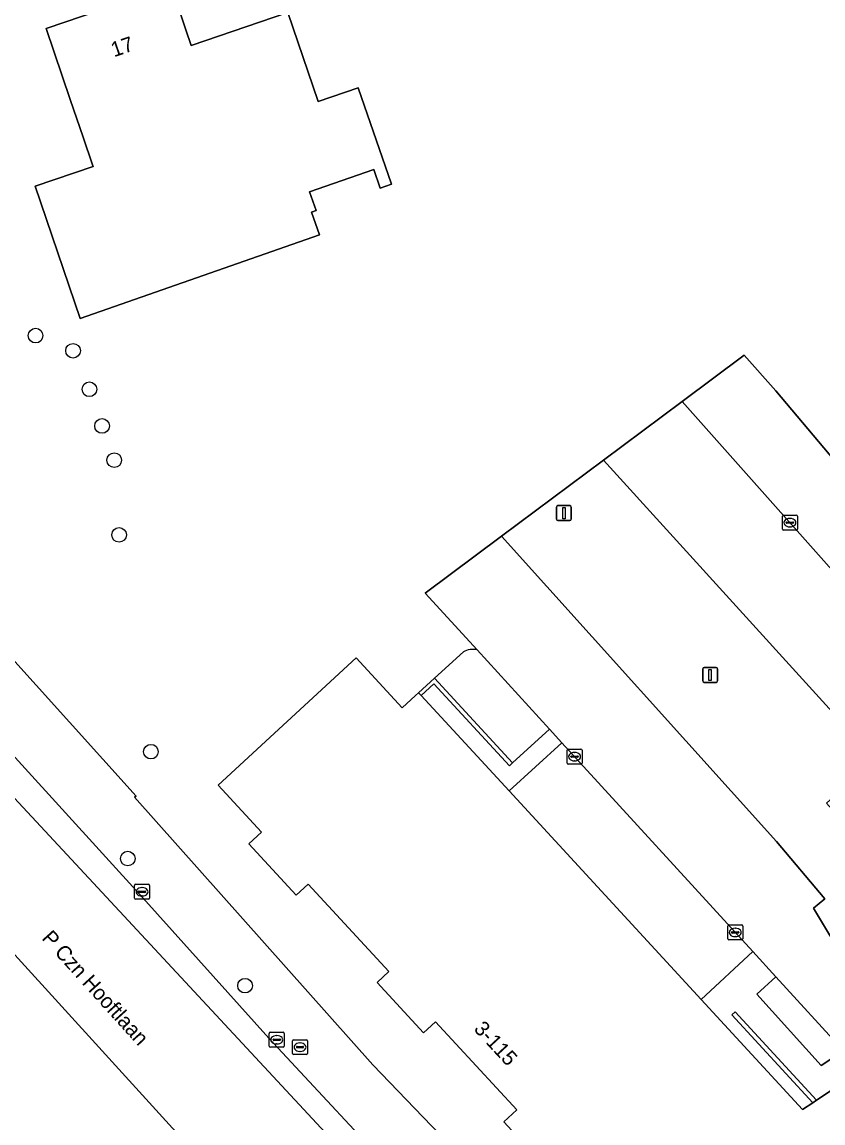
# Model space of a CAD drawing. Extents: x 161087 to 161926, y 382572 to 383873.
# Drawn here: x 161601.8 to 161655.3, y 382684.1 to 382757.7 of the extents above; entities that cross this region are included whole.
import ezdxf

# ---------------------------------------------------------------- set-up
doc = ezdxf.new("R2010")
doc.units = 0
for name, color, linetype in [('IMGEO_Boom', 7, 'Continuous'), ('IMGEO_Erf', 7, 'Continuous'), ('IMGEO_Groenvoorziening', 7, 'Continuous'), ('IMGEO_Kolk', 7, 'Continuous'), ('IMGEO_Lichtmast', 7, 'Continuous'), ('IMGEO_Muur', 7, 'Continuous'), ('IMGEO_Openbare_ruimte_label', 7, 'Continuous'), ('IMGEO_Pand', 7, 'Continuous'), ('IMGEO_Pand_nummerreeks', 7, 'Continuous'), ('IMGEO_Parkeervlak_open', 7, 'Continuous'), ('IMGEO_Rijbaan_lokaal_gesloten', 7, 'Continuous'), ('IMGEO_Rijbaan_lokaal_open', 7, 'Continuous'), ('IMGEO_Rioolput', 7, 'Continuous'), ('IMGEO_Terreindeel_open', 7, 'Continuous'), ('IMGEO_Voetpad_open', 7, 'Continuous')]:
    doc.layers.add(name, color=color, linetype=linetype)

msp = doc.modelspace()

# ---------------------------------------------------------------- linework, layer by layer
at = {"layer": 'IMGEO_Boom'}
for centre in [(161602.7, 382736.735), (161605.203, 382735.724), (161606.3, 382733.148), (161607.142, 382730.699), (161607.958, 382728.415), (161608.285, 382723.426), (161610.405, 382708.942), (161608.861, 382701.802), (161616.697, 382693.31)]:
    msp.add_circle(centre, 0.489, dxfattribs=at)
at = {"layer": 'IMGEO_Erf'}
msp.add_lwpolyline([(161626.489, 382746.857), (161625.734, 382746.594), (161625.299, 382747.84), (161621.008, 382746.343), (161621.443, 382745.096), (161621.131, 382744.988), (161621.665, 382743.458), (161605.682, 382737.882), (161602.665, 382746.708), (161606.548, 382748.035), (161606.513, 382748.138), (161605.876, 382750), (161605.018, 382752.511), (161603.401, 382757.242), (161611.749, 382760.095), (161612.227, 382758.695), (161612.749, 382757.17), (161613.106, 382756.121), (161619.557, 382758.324), (161621.59, 382752.37), (161624.249, 382753.278)], close=True, dxfattribs=at)
for points in [[(161573.649, 382745.916), (161575.439, 382743.417), (161575.924, 382742.835), (161583.433, 382734.169), (161584.982, 382732.778), (161585.192, 382732.858), (161589.562, 382727.999), (161609.424, 382705.975), (161609.305, 382705.895), (161625.238, 382688.024), (161643.165, 382669.38), (161647.852, 382664.262), (161649.374, 382662.6), (161650.008, 382663.023), (161699.247, 382695.877)], [(161632.202, 382715.736), (161628.729, 382719.538), (161633.825, 382723.334), (161640.645, 382728.413), (161645.915, 382732.339), (161650.055, 382735.423), (161652.164, 382733.056), (161661.072, 382722.472), (161675.692, 382731.244), (161680.06, 382733.622), (161682.663, 382729.735), (161700.929, 382702.454), (161713.52, 382710.932)], [(161637.133, 382680.802), (161633.986, 382684.208), (161634.853, 382685.008), (161629.418, 382690.891), (161628.626, 382690.16), (161625.521, 382693.521), (161626.311, 382694.251), (161620.913, 382700.093), (161620.113, 382699.354), (161616.946, 382702.781), (161617.802, 382703.572), (161614.909, 382706.703), (161624.113, 382715.206), (161627.197, 382711.868), (161628.092, 382712.692), (161628.297, 382712.881), (161629.361, 382713.862), (161631.288, 382715.608)]]:
    msp.add_lwpolyline(points, dxfattribs=at)
msp.add_arc((161631.903, 382714.542), 1.231, 75.94681, 119.99733, dxfattribs=at)
at = {"layer": 'IMGEO_Groenvoorziening'}
msp.add_lwpolyline([(161631.288, 382715.608), (161629.361, 382713.862), (161634.574, 382708.203), (161637.045, 382710.44), (161632.202, 382715.736)], dxfattribs=at)
msp.add_lwpolyline([(161637.868, 382709.539), (161634.338, 382706.324), (161647.175, 382692.39), (161650.622, 382695.592)], close=True, dxfattribs=at)
msp.add_arc((161631.903, 382714.542), 1.231, 75.94681, 119.99733, dxfattribs=at)
at = {"layer": 'IMGEO_Kolk'}
for p, q in [((161652.607, 382723.815), (161652.607, 382724.667)), ((161652.682, 382724.741), (161653.534, 382724.741)), ((161653.608, 382724.667), (161653.608, 382723.815)), ((161652.866, 382724.235), (161652.866, 382724.247)), ((161653.304, 382724.198), (161652.906, 382724.198)), ((161652.909, 382724.284), (161653.307, 382724.284)), ((161653.118, 382723.961), (161653.093, 382723.961)), ((161653.095, 382724.521), (161653.12, 382724.521)), ((161653.35, 382724.247), (161653.35, 382724.235)), ((161653.534, 382723.741), (161652.682, 382723.741)), ((161638.294, 382709.109), (161639.146, 382709.109)), ((161638.219, 382708.183), (161638.219, 382709.035)), ((161638.478, 382708.603), (161638.478, 382708.615)), ((161638.916, 382708.566), (161638.518, 382708.566)), ((161638.521, 382708.652), (161638.919, 382708.652)), ((161638.707, 382708.889), (161638.732, 382708.889)), ((161638.962, 382708.615), (161638.962, 382708.603)), ((161639.22, 382709.035), (161639.22, 382708.183)), ((161639.146, 382708.109), (161638.294, 382708.109)), ((161638.73, 382708.329), (161638.705, 382708.329)), ((161609.316, 382699.156), (161609.316, 382700.008)), ((161609.391, 382700.082), (161610.243, 382700.082)), ((161609.575, 382699.576), (161609.575, 382699.588)), ((161610.013, 382699.539), (161609.615, 382699.539)), ((161609.618, 382699.625), (161610.016, 382699.625)), ((161609.804, 382699.862), (161609.829, 382699.862)), ((161610.059, 382699.588), (161610.059, 382699.576)), ((161610.317, 382700.008), (161610.317, 382699.156)), ((161610.243, 382699.082), (161609.391, 382699.082)), ((161609.827, 382699.302), (161609.802, 382699.302)), ((161649.029, 382697.369), (161649.881, 382697.369)), ((161648.954, 382696.443), (161648.954, 382697.295)), ((161649.213, 382696.863), (161649.213, 382696.875)), ((161649.651, 382696.826), (161649.253, 382696.826)), ((161649.256, 382696.912), (161649.654, 382696.912)), ((161649.465, 382696.589), (161649.44, 382696.589)), ((161649.442, 382697.149), (161649.467, 382697.149)), ((161649.697, 382696.875), (161649.697, 382696.863)), ((161649.955, 382697.295), (161649.955, 382696.443)), ((161649.881, 382696.369), (161649.029, 382696.369)), ((161618.319, 382689.273), (161618.319, 382690.125)), ((161618.394, 382690.199), (161619.246, 382690.199)), ((161618.807, 382689.979), (161618.832, 382689.979)), ((161619.32, 382690.125), (161619.32, 382689.273)), ((161618.578, 382689.693), (161618.578, 382689.705)), ((161619.016, 382689.656), (161618.618, 382689.656)), ((161618.621, 382689.742), (161619.019, 382689.742)), ((161618.83, 382689.419), (161618.805, 382689.419)), ((161619.062, 382689.705), (161619.062, 382689.693)), ((161619.246, 382689.199), (161618.394, 382689.199))]:
    msp.add_line(p, q, dxfattribs=at)
for points in [[(161652.607, 382723.815), (161652.607, 382724.667)], [(161652.682, 382724.741), (161653.534, 382724.741)], [(161653.608, 382724.667), (161653.608, 382723.815)], [(161653.534, 382723.741), (161652.682, 382723.741)], [(161638.294, 382709.109), (161639.146, 382709.109)], [(161638.219, 382708.183), (161638.219, 382709.035)], [(161639.22, 382709.035), (161639.22, 382708.183)], [(161639.146, 382708.109), (161638.294, 382708.109)], [(161609.316, 382699.156), (161609.316, 382700.008)], [(161609.391, 382700.082), (161610.243, 382700.082)], [(161610.317, 382700.008), (161610.317, 382699.156)], [(161610.243, 382699.082), (161609.391, 382699.082)], [(161649.029, 382697.369), (161649.881, 382697.369)], [(161648.954, 382696.443), (161648.954, 382697.295)], [(161649.955, 382697.295), (161649.955, 382696.443)], [(161649.881, 382696.369), (161649.029, 382696.369)], [(161618.319, 382689.273), (161618.319, 382690.125)], [(161618.394, 382690.199), (161619.246, 382690.199)], [(161619.32, 382690.125), (161619.32, 382689.273)], [(161619.246, 382689.199), (161618.394, 382689.199)]]:
    msp.add_lwpolyline(points, dxfattribs=at)
for centre, radius, start, end in [((161652.684, 382724.665), 0.0765, 91.55205, 178.44795), ((161652.684, 382724.665), 0.0765, 91.55205, 178.44795), ((161653.532, 382724.665), 0.0765, 1.55205, 88.44795), ((161653.532, 382724.665), 0.0765, 1.55205, 88.44795), ((161652.684, 382723.817), 0.0765, 181.55205, 268.44795), ((161652.684, 382723.817), 0.0765, 181.55205, 268.44795), ((161652.906, 382724.244), 0.0403, 85.87752, 175.75265), ((161652.903, 382724.234), 0.0366, 178.93798, 274.71019), ((161653.307, 382724.241), 0.043, 264.86636, 352.45326), ((161653.311, 382724.246), 0.0386, 1.73085, 96.63898), ((161653.532, 382723.817), 0.0765, 271.55205, 358.44795), ((161653.532, 382723.817), 0.0765, 271.55205, 358.44795), ((161638.296, 382709.033), 0.0765, 91.55205, 178.44795), ((161638.296, 382709.033), 0.0765, 91.55205, 178.44795), ((161639.144, 382709.033), 0.0765, 1.55205, 88.44795), ((161639.144, 382709.033), 0.0765, 1.55205, 88.44795), ((161638.518, 382708.612), 0.0403, 85.87752, 175.75265), ((161638.515, 382708.602), 0.0366, 178.93798, 274.71019), ((161638.919, 382708.609), 0.043, 264.86636, 352.45326), ((161638.923, 382708.614), 0.0386, 1.73085, 96.63898), ((161638.296, 382708.185), 0.0765, 181.55205, 268.44795), ((161638.296, 382708.185), 0.0765, 181.55205, 268.44795), ((161639.144, 382708.185), 0.0765, 271.55205, 358.44795), ((161639.144, 382708.185), 0.0765, 271.55205, 358.44795), ((161609.393, 382700.006), 0.0765, 91.55205, 178.44795), ((161609.393, 382700.006), 0.0765, 91.55205, 178.44795), ((161609.615, 382699.585), 0.0403, 85.87752, 175.75265), ((161609.612, 382699.575), 0.0366, 178.93798, 274.71019), ((161610.016, 382699.582), 0.043, 264.86636, 352.45326), ((161610.02, 382699.587), 0.0386, 1.73085, 96.63898), ((161610.241, 382700.006), 0.0765, 1.55205, 88.44795), ((161610.241, 382700.006), 0.0765, 1.55205, 88.44795), ((161609.393, 382699.158), 0.0765, 181.55205, 268.44795), ((161609.393, 382699.158), 0.0765, 181.55205, 268.44795), ((161610.241, 382699.158), 0.0765, 271.55205, 358.44795), ((161610.241, 382699.158), 0.0765, 271.55205, 358.44795), ((161649.031, 382697.293), 0.0765, 91.55205, 178.44795), ((161649.031, 382697.293), 0.0765, 91.55205, 178.44795), ((161649.879, 382697.293), 0.0765, 1.55205, 88.44795), ((161649.879, 382697.293), 0.0765, 1.55205, 88.44795), ((161649.253, 382696.872), 0.0403, 85.87752, 175.75265), ((161649.25, 382696.862), 0.0366, 178.93798, 274.71019), ((161649.654, 382696.869), 0.043, 264.86636, 352.45326), ((161649.658, 382696.874), 0.0386, 1.73085, 96.63898), ((161649.031, 382696.445), 0.0765, 181.55205, 268.44795), ((161649.031, 382696.445), 0.0765, 181.55205, 268.44795), ((161649.879, 382696.445), 0.0765, 271.55205, 358.44795), ((161649.879, 382696.445), 0.0765, 271.55205, 358.44795), ((161618.396, 382690.123), 0.0765, 91.55205, 178.44795), ((161618.396, 382690.123), 0.0765, 91.55205, 178.44795), ((161619.244, 382690.123), 0.0765, 1.55205, 88.44795), ((161619.244, 382690.123), 0.0765, 1.55205, 88.44795), ((161618.396, 382689.275), 0.0765, 181.55205, 268.44795), ((161618.396, 382689.275), 0.0765, 181.55205, 268.44795), ((161618.618, 382689.702), 0.0403, 85.87752, 175.75265), ((161618.615, 382689.692), 0.0366, 178.93798, 274.71019), ((161619.019, 382689.699), 0.043, 264.86636, 352.45326), ((161619.023, 382689.704), 0.0386, 1.73085, 96.63898), ((161619.244, 382689.275), 0.0765, 271.55205, 358.44795), ((161619.244, 382689.275), 0.0765, 271.55205, 358.44795)]:
    msp.add_arc(centre, radius, start, end, dxfattribs=at)
for centre, major_axis, ratio, start_param, end_param in [((161653.094, 382724.241), (-0.387, 0.002), 0.722429, 4.712389, 7.853982), ((161653.119, 382724.241), (-0.39, 0.002), 0.717154, 1.570796, 4.712389), ((161638.706, 382708.609), (-0.387, 0.002), 0.722429, 4.712389, 7.853982), ((161638.731, 382708.609), (-0.39, 0.002), 0.717154, 1.570796, 4.712389), ((161609.803, 382699.582), (-0.387, 0.002), 0.722429, 4.712389, 7.853982), ((161609.828, 382699.582), (-0.39, 0.002), 0.717154, 1.570796, 4.712389), ((161649.441, 382696.869), (-0.387, 0.002), 0.722429, 4.712389, 7.853982), ((161649.466, 382696.869), (-0.39, 0.002), 0.717154, 1.570796, 4.712389), ((161618.806, 382689.699), (-0.387, 0.002), 0.722429, 4.712389, 7.853982), ((161618.831, 382689.699), (-0.39, 0.002), 0.717154, 1.570796, 4.712389)]:
    msp.add_ellipse(centre, major_axis=major_axis, ratio=ratio, start_param=start_param, end_param=end_param, dxfattribs=at)
at = {"layer": 'IMGEO_Lichtmast'}
for p, q in [((161637.511, 382724.479), (161637.511, 382725.279)), ((161637.511, 382725.279), (161637.511, 382724.479)), ((161637.611, 382725.379), (161638.401, 382725.379)), ((161638.401, 382725.379), (161637.611, 382725.379)), ((161638.501, 382725.279), (161638.501, 382724.479)), ((161638.501, 382724.479), (161638.501, 382725.279)), ((161638.401, 382724.379), (161637.611, 382724.379)), ((161637.611, 382724.379), (161638.401, 382724.379)), ((161647.28, 382713.667), (161647.28, 382714.467)), ((161647.28, 382714.467), (161647.28, 382713.667)), ((161647.38, 382714.567), (161648.17, 382714.567)), ((161648.17, 382714.567), (161647.38, 382714.567)), ((161648.27, 382714.467), (161648.27, 382713.667)), ((161648.27, 382713.667), (161648.27, 382714.467)), ((161648.17, 382713.567), (161647.38, 382713.567)), ((161647.38, 382713.567), (161648.17, 382713.567))]:
    msp.add_line(p, q, dxfattribs=at)
for points in [[(161637.931, 382725.254), (161638.081, 382725.254), (161638.081, 382724.504), (161637.931, 382724.504), (161637.931, 382725.254)], [(161647.7, 382714.442), (161647.85, 382714.442), (161647.85, 382713.692), (161647.7, 382713.692), (161647.7, 382714.442)]]:
    msp.add_lwpolyline(points, dxfattribs=at)
for centre, start, end in [((161637.611, 382725.279), 90, 180), ((161637.611, 382725.279), 90, 180), ((161638.401, 382725.279), 0, 90), ((161638.401, 382725.279), 360, 90), ((161637.611, 382724.479), 180, 270), ((161637.611, 382724.479), 180, 270), ((161638.401, 382724.479), 270, 0), ((161638.401, 382724.479), 270, 0), ((161647.38, 382714.467), 90, 180), ((161647.38, 382714.467), 90, 180), ((161648.17, 382714.467), 0, 90), ((161648.17, 382714.467), 360, 90), ((161647.38, 382713.667), 180, 270), ((161647.38, 382713.667), 180, 270), ((161648.17, 382713.667), 270, 0), ((161648.17, 382713.667), 270, 0)]:
    msp.add_arc(centre, 0.1, start, end, dxfattribs=at)
at = {"layer": 'IMGEO_Muur'}
for points in [[(161629.313, 382713.483), (161634.359, 382708.005), (161634.574, 382708.203), (161629.361, 382713.862), (161628.297, 382712.881), (161628.463, 382712.7)], [(161654.886, 382685.652), (161649.445, 382691.558), (161649.237, 382691.365), (161654.648, 382685.492)]]:
    msp.add_lwpolyline(points, close=True, dxfattribs=at)
at = {"layer": 'IMGEO_Pand'}
msp.add_lwpolyline([(161624.249, 382753.278), (161621.59, 382752.37), (161619.557, 382758.324), (161613.106, 382756.121), (161612.749, 382757.17), (161612.227, 382758.695), (161611.749, 382760.095), (161603.401, 382757.242), (161605.018, 382752.511), (161605.876, 382750), (161606.513, 382748.138), (161606.548, 382748.035), (161602.665, 382746.708), (161605.682, 382737.882), (161621.665, 382743.458), (161621.131, 382744.988), (161621.443, 382745.096), (161621.008, 382746.343), (161625.299, 382747.84), (161625.734, 382746.594), (161626.489, 382746.857)], close=True, dxfattribs=at)
msp.add_lwpolyline([(161683.371, 382704.641), (161654.886, 382685.652), (161654.648, 382685.492), (161653.956, 382685.031), (161647.175, 382692.39), (161634.338, 382706.324), (161628.463, 382712.7), (161628.297, 382712.881), (161628.092, 382712.692), (161627.197, 382711.868), (161624.113, 382715.206), (161614.909, 382706.703), (161617.802, 382703.572), (161616.946, 382702.781), (161620.113, 382699.354), (161620.913, 382700.093), (161626.311, 382694.251), (161625.521, 382693.521), (161628.626, 382690.16), (161629.418, 382690.891), (161634.853, 382685.008), (161633.986, 382684.208), (161637.133, 382680.802)], dxfattribs=at)
at = {"layer": 'IMGEO_Parkeervlak_open'}
for points in [[(161652.164, 382733.056), (161650.055, 382735.423), (161645.915, 382732.339), (161659.826, 382716.672), (161682.663, 382729.735), (161680.06, 382733.622), (161675.692, 382731.244), (161661.072, 382722.472)], [(161686.783, 382714.893), (161682.173, 382721.921), (161660.241, 382707.326), (161662.336, 382704.08), (161659.264, 382701.333), (161655.544, 382705.493), (161658.818, 382708.421), (161640.645, 382728.413), (161633.825, 382723.334), (161652.223, 382702.935), (161655.434, 382699.108), (161654.688, 382698.482), (161656.868, 382694.863)]]:
    msp.add_lwpolyline(points, close=True, dxfattribs=at)
at = {"layer": 'IMGEO_Rijbaan_lokaal_gesloten'}
for points in [[(161563.602, 382736.77), (161592.087, 382705.487), (161622.627, 382671.947), (161661.586, 382630.771), (161701.238, 382588.176), (161728.827, 382571.874), (161779.525, 382578.285), (161779.123, 382582.55), (161766.2, 382581.371), (161761.033, 382580.909)], [(161645.804, 382661.238), (161642.351, 382664.758), (161637.265, 382669.796), (161627.567, 382679.823), (161618.288, 382689.808), (161609.858, 382699.184), (161593.448, 382717.185), (161584.083, 382727.396), (161580.691, 382731.313), (161580.138, 382731.973), (161578.104, 382734.877), (161576.275, 382733.561)], [(161582.233, 382726.427), (161583.729, 382724.844), (161586.909, 382721.287), (161627.635, 382677.479), (161643.825, 382659.427), (161680.185, 382618.886)], [(161709.816, 382586.053), (161680.185, 382618.886), (161643.825, 382659.427), (161627.635, 382677.479), (161586.909, 382721.287), (161583.729, 382724.844), (161582.233, 382726.427)]]:
    msp.add_lwpolyline(points, dxfattribs=at)
at = {"layer": 'IMGEO_Rijbaan_lokaal_open'}
for points in [[(161659.826, 382716.672), (161645.915, 382732.339), (161640.645, 382728.413), (161658.818, 382708.421)], [(161656.868, 382694.863), (161654.688, 382698.482), (161655.434, 382699.108), (161652.223, 382702.935), (161633.825, 382723.334), (161628.729, 382719.538), (161632.202, 382715.736), (161637.045, 382710.44), (161637.868, 382709.539), (161650.622, 382695.592), (161652.162, 382693.908), (161656.689, 382688.957)]]:
    msp.add_lwpolyline(points, dxfattribs=at)
at = {"layer": 'IMGEO_Rioolput'}
for p, q in [((161619.87, 382688.777), (161619.87, 382689.629)), ((161619.945, 382689.703), (161620.797, 382689.703)), ((161620.172, 382689.246), (161620.57, 382689.246)), ((161620.358, 382689.483), (161620.383, 382689.483)), ((161620.871, 382689.629), (161620.871, 382688.777)), ((161620.797, 382688.703), (161619.945, 382688.703)), ((161620.129, 382689.197), (161620.129, 382689.209)), ((161620.567, 382689.16), (161620.169, 382689.16)), ((161620.381, 382688.923), (161620.356, 382688.923)), ((161620.613, 382689.209), (161620.613, 382689.197))]:
    msp.add_line(p, q, dxfattribs=at)
for points in [[(161619.87, 382688.777), (161619.87, 382689.629)], [(161619.945, 382689.703), (161620.797, 382689.703)], [(161620.871, 382689.629), (161620.871, 382688.777)], [(161620.797, 382688.703), (161619.945, 382688.703)]]:
    msp.add_lwpolyline(points, dxfattribs=at)
for centre, radius, start, end in [((161619.947, 382689.627), 0.0765, 91.55205, 178.44795), ((161619.947, 382689.627), 0.0765, 91.55205, 178.44795), ((161620.169, 382689.206), 0.0403, 85.87752, 175.75265), ((161620.574, 382689.208), 0.0386, 1.73085, 96.63898), ((161620.795, 382689.627), 0.0765, 1.55205, 88.44795), ((161620.795, 382689.627), 0.0765, 1.55205, 88.44795), ((161619.947, 382688.779), 0.0765, 181.55205, 268.44795), ((161619.947, 382688.779), 0.0765, 181.55205, 268.44795), ((161620.166, 382689.196), 0.0366, 178.93798, 274.71019), ((161620.57, 382689.203), 0.043, 264.86636, 352.45326), ((161620.795, 382688.779), 0.0765, 271.55205, 358.44795), ((161620.795, 382688.779), 0.0765, 271.55205, 358.44795)]:
    msp.add_arc(centre, radius, start, end, dxfattribs=at)
for centre, major_axis, ratio, start_param, end_param in [((161620.357, 382689.203), (-0.387, 0.002), 0.722429, 4.712389, 7.853982), ((161620.382, 382689.203), (-0.39, 0.002), 0.717154, 1.570796, 4.712389)]:
    msp.add_ellipse(centre, major_axis=major_axis, ratio=ratio, start_param=start_param, end_param=end_param, dxfattribs=at)
at = {"layer": 'IMGEO_Terreindeel_open'}
msp.add_lwpolyline([(161656.689, 382688.957), (161652.162, 382693.908), (161650.887, 382692.734), (161655.206, 382687.967)], close=True, dxfattribs=at)
at = {"layer": 'IMGEO_Voetpad_open'}
for points in [[(161585.192, 382732.858), (161584.982, 382732.778), (161583.433, 382734.169), (161575.924, 382742.835), (161575.439, 382743.417), (161573.649, 382745.916), (161571.694, 382744.598), (161573.766, 382741.336), (161578.104, 382734.877), (161580.138, 382731.973), (161580.691, 382731.313), (161584.083, 382727.396), (161593.448, 382717.185), (161609.858, 382699.184), (161618.288, 382689.808), (161627.567, 382679.823), (161637.265, 382669.796), (161642.351, 382664.758), (161645.804, 382661.238)], [(161651.703, 382659.86), (161649.374, 382662.6), (161647.852, 382664.262), (161643.165, 382669.38), (161625.238, 382688.024), (161609.305, 382705.895), (161609.424, 382705.975), (161589.562, 382727.999), (161585.192, 382732.858)]]:
    msp.add_lwpolyline(points, dxfattribs=at)
for points in [[(161629.313, 382713.483), (161628.463, 382712.7), (161634.338, 382706.324), (161637.868, 382709.539), (161637.045, 382710.44), (161634.574, 382708.203), (161634.359, 382708.005)], [(161683.371, 382704.641), (161683.55, 382704.552), (161686.736, 382706.676), (161687.438, 382705.623), (161691.115, 382708.074), (161689.336, 382710.75), (161656.689, 382688.957), (161655.206, 382687.967), (161650.887, 382692.734), (161652.162, 382693.908), (161650.622, 382695.592), (161647.175, 382692.39), (161653.956, 382685.031), (161654.648, 382685.492), (161649.237, 382691.365), (161649.445, 382691.558), (161654.886, 382685.652)]]:
    msp.add_lwpolyline(points, close=True, dxfattribs=at)

# ---------------------------------------------------------------- texts
at = {"layer": 'IMGEO_Openbare_ruimte_label'}
msp.add_text('P Czn Hooftlaan', height=1, rotation=312.12344, dxfattribs=at).set_placement((161603.067, 382696.449))
at = {"layer": 'IMGEO_Pand_nummerreeks'}
for s, rotation, p in [('17', 18.8675, (161607.94, 382755.326)), ('3-115', 312.73098, (161631.933, 382690.38))]:
    msp.add_text(s, height=1, rotation=rotation, dxfattribs=at).set_placement(p)

doc.saveas('drawing.dxf')
